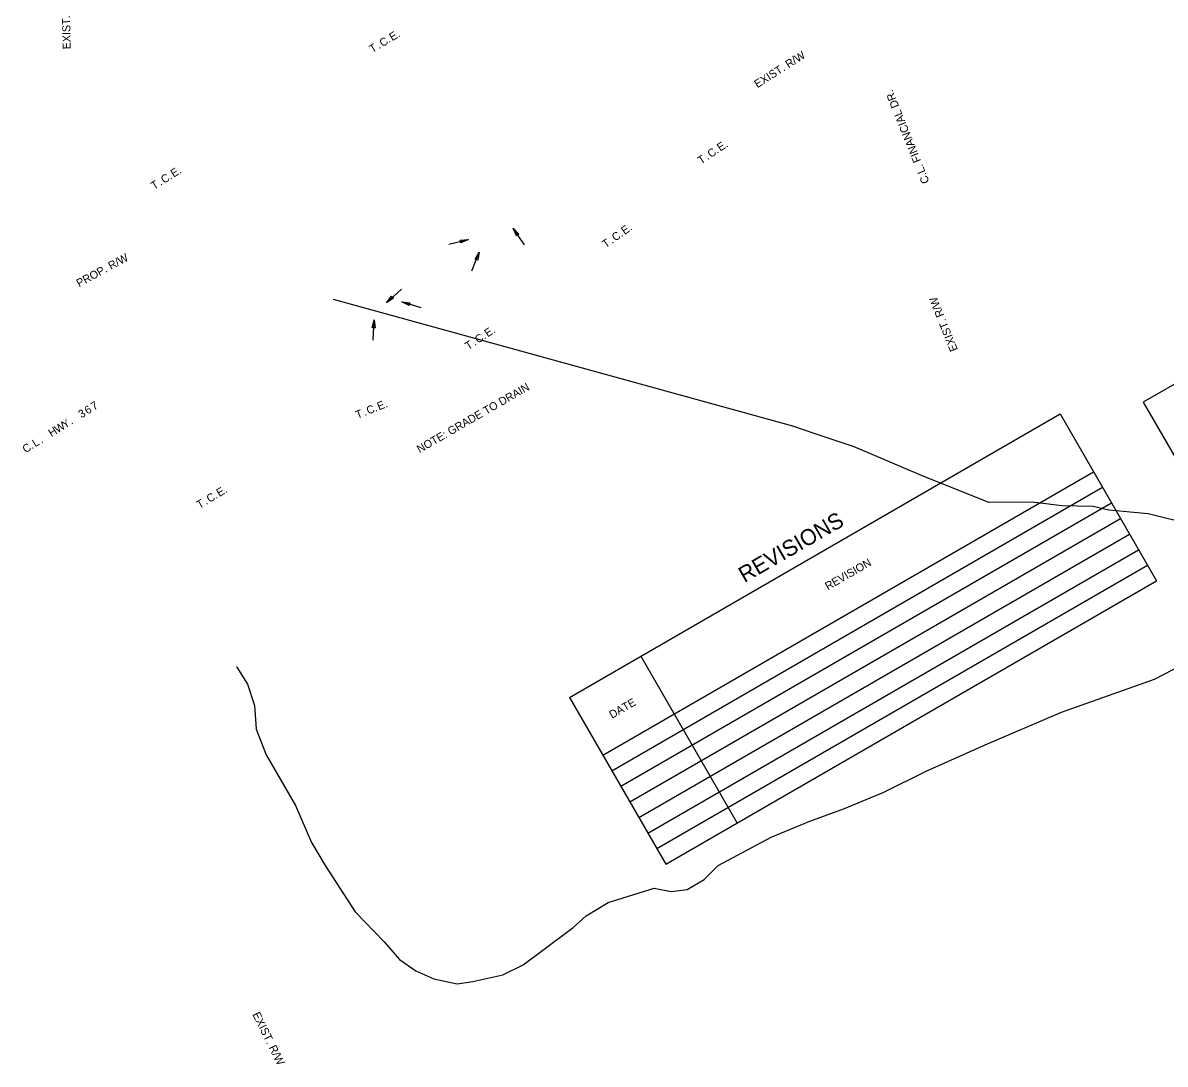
# Model space of a CAD drawing. Extents: x 1293866 to 1295382, y 223015 to 224618.
# Drawn here: x 1293866 to 1294723, y 223015 to 223796 of the extents above; entities that cross this region are included whole.
import ezdxf

# ---------------------------------------------------------------- set-up
doc = ezdxf.new("R2010")
doc.units = 0
for name, color, linetype in [('1', 7, 'Continuous'), ('10Tan10', 7, 'Continuous'), ('19', 7, 'Continuous'), ('43', 7, 'Continuous'), ('Default', 7, 'Continuous'), ('R_Draft', 7, 'Continuous'), ('S_TREE', 7, 'Continuous')]:
    doc.layers.add(name, color=color, linetype=linetype)

msp = doc.modelspace()

# ---------------------------------------------------------------- linework, layer by layer
at = {"layer": '1'}
msp.add_line((1295002.97, 223683.01), (1294706.22, 223511.68), dxfattribs=at)
msp.add_lwpolyline([(1294706.22, 223511.68), (1294766.75, 223406.85), (1295063.5, 223578.18)], dxfattribs=at)
at = {"layer": '19'}
for p, q in [((1294275.84, 223290.28), (1294643.9, 223502.78)), ((1294643.9, 223502.78), (1294716.15, 223377.64)), ((1294300.84, 223246.98), (1294668.9, 223459.48)), ((1294307.59, 223235.29), (1294675.65, 223447.79)), ((1294314.34, 223223.59), (1294682.4, 223436.09)), ((1294321.09, 223211.9), (1294689.15, 223424.4)), ((1294321.09, 223211.9), (1294689.15, 223424.4)), ((1294327.84, 223200.21), (1294695.9, 223412.71)), ((1294334.59, 223188.52), (1294702.65, 223401.02)), ((1294341.34, 223176.83), (1294709.4, 223389.33)), ((1294348.09, 223165.14), (1294716.15, 223377.64)), ((1294329.37, 223321.18), (1294401.62, 223196.04)), ((1294275.84, 223290.28), (1294348.09, 223165.14))]:
    msp.add_line(p, q, dxfattribs=at)
at = {"layer": '43'}
for p, q in [((1294233.62, 223642.03), (1294237.97, 223637.66)), ((1294236.21, 223636.44), (1294233.62, 223642.03)), ((1294194.07, 223633.22), (1294200.23, 223633.58)), ((1294194.57, 223631.13), (1294194.07, 223633.22)), ((1294200.23, 223633.58), (1294194.57, 223631.13)), ((1294237.97, 223637.66), (1294236.21, 223636.44)), ((1294205.08, 223618.97), (1294208.29, 223624.24)), ((1294208.29, 223624.24), (1294207.08, 223618.19)), ((1294207.08, 223618.19), (1294205.08, 223618.97)), ((1294138.66, 223586.24), (1294142.45, 223591.11)), ((1294143.89, 223589.52), (1294138.66, 223586.24)), ((1294142.45, 223591.11), (1294143.89, 223589.52)), ((1294150.13, 223586.84), (1294156.25, 223586.09)), ((1294155.63, 223584.04), (1294150.13, 223586.84)), ((1294156.25, 223586.09), (1294155.63, 223584.04)), ((1294128.09, 223567.34), (1294129.42, 223573.37)), ((1294129.42, 223573.37), (1294130.24, 223567.26)), ((1294130.24, 223567.26), (1294128.09, 223567.34))]:
    msp.add_line(p, q, dxfattribs=at)
for points in [[(1294242.29, 223629.57), (1294233.62, 223642.03)], [(1294185.45, 223630.08), (1294200.23, 223633.58)], [(1294202.77, 223610.09), (1294208.29, 223624.24)], [(1294149.93, 223596.42), (1294138.66, 223586.24)], [(1294164.66, 223582.4), (1294150.13, 223586.84)], [(1294128.79, 223558.2), (1294129.42, 223573.37)]]:
    msp.add_lwpolyline(points, dxfattribs=at)
at = {"layer": 'S_TREE'}
for points in [[(1294741.11, 223420.17), (1294709.95, 223427.78), (1294680.44, 223430.53), (1294668.71, 223433.36), (1294645.06, 223433.94), (1294623.05, 223436.57), (1294590.5, 223436.36), (1294539.79, 223456.62), (1294489.32, 223478.03), (1294460.84, 223487.63), (1294443.51, 223493.56), (1294098.95, 223588.59)], [(1294741.11, 223420.17), (1294709.95, 223427.78), (1294680.44, 223430.53), (1294668.71, 223433.36), (1294645.06, 223433.94), (1294623.05, 223436.57), (1294590.5, 223436.36), (1294539.79, 223456.62), (1294489.32, 223478.03), (1294460.84, 223487.63), (1294443.51, 223493.56), (1294098.95, 223588.59)], [(1294026.12, 223313.39), (1294026.44, 223312.93), (1294034.41, 223300.06), (1294039.65, 223284.29), (1294040.93, 223266.46), (1294048.46, 223247.28), (1294070.41, 223209.15), (1294082.4, 223181.33), (1294092.61, 223164.13), (1294115.34, 223129.4), (1294136.94, 223106.87), (1294148.52, 223093.75), (1294160.78, 223085.28), (1294174.29, 223079.08), (1294191.59, 223075.33), (1294203.5, 223077.21), (1294225.94, 223082.16), (1294241.14, 223089.78), (1294255.85, 223100.7), (1294278.59, 223117.58), (1294288.45, 223126.49), (1294304.9, 223136.38), (1294339.34, 223147.18), (1294352.2, 223144.65), (1294364.26, 223146.16), (1294376.91, 223153.6), (1294387.43, 223164.09), (1294427.14, 223185.39), (1294456.24, 223197.48), (1294482.07, 223206.89), (1294511.54, 223219.13), (1294543.44, 223235), (1294587.74, 223254.71), (1294644.84, 223279.28), (1294714.57, 223303.99), (1294748.77, 223321.6)], [(1294026.12, 223313.39), (1294026.44, 223312.93), (1294034.41, 223300.06), (1294039.65, 223284.29), (1294040.93, 223266.46), (1294048.46, 223247.28), (1294070.41, 223209.15), (1294082.4, 223181.33), (1294092.61, 223164.13), (1294115.34, 223129.4), (1294136.94, 223106.87), (1294148.52, 223093.75), (1294160.78, 223085.28), (1294174.29, 223079.08), (1294191.59, 223075.33), (1294203.5, 223077.21), (1294225.94, 223082.16), (1294241.14, 223089.78), (1294255.85, 223100.7), (1294278.59, 223117.58), (1294288.45, 223126.49), (1294304.9, 223136.38), (1294339.34, 223147.18), (1294352.2, 223144.65), (1294364.26, 223146.16), (1294376.91, 223153.6), (1294387.43, 223164.09), (1294427.14, 223185.39), (1294456.24, 223197.48), (1294482.07, 223206.89), (1294511.54, 223219.13), (1294543.44, 223235), (1294587.74, 223254.71), (1294644.84, 223279.28), (1294714.57, 223303.99), (1294748.77, 223321.6)]]:
    msp.add_lwpolyline(points, dxfattribs=at)

# ---------------------------------------------------------------- texts
at = {"layer": '10Tan10'}
for s, rotation, p in [('EXIST. R/W & C/A', 91.19347, (1293901.92, 223776.28)), ('EXIST. R/W', 32.42629, (1294416.84, 223747.02)), ('PROP. R/W', 28.60191, (1293908.19, 223597.75)), ('EXIST. R/W', 111.79541, (1294567.23, 223551.03)), ('EXIST. R/W', 296.21548, (1294038.04, 223052.53))]:
    msp.add_text(s, height=6, rotation=rotation, dxfattribs=at).set_placement(p)
at = {"layer": '19'}
for s, height, p in [('REVISIONS', 12, (1294407.12, 223375.89)), ('REVISION', 6, (1294469.71, 223370.45)), ('DATE', 6, (1294307.85, 223274.12))]:
    msp.add_text(s, height=height, rotation=30.00011, dxfattribs=at).set_placement(p)
at = {"layer": 'Default'}
for s, rotation, p in [('C.L. FINANCIAL DR.', 111.83333, (1294545.96, 223676.88)), ('7', 31.99396, (1293919.33, 223505.25)), ('3', 31.99396, (1293909.96, 223499.39)), ('6', 31.99396, (1293914.53, 223502.25)), ('W', 31.99396, (1293892.05, 223488.2)), ('Y', 31.99396, (1293897.5, 223491.61)), ('.', 31.99396, (1293902.39, 223494.66)), ('H', 31.99396, (1293887.48, 223485.35)), ('C', 31.99396, (1293868.05, 223473.21)), ('L', 31.99396, (1293875.34, 223477.76)), ('.', 31.99396, (1293872.86, 223476.21)), ('.', 31.99396, (1293879.91, 223480.62))]:
    msp.add_text(s, height=6, rotation=rotation, dxfattribs=at).set_placement(p)
at = {"layer": 'R_Draft'}
for s, rotation, p in [('E', 30.9348, (1294142.99, 223782.24)), ('.', 30.9348, (1294147.61, 223785.01)), ('T', 30.9348, (1294128.08, 223773.3)), ('.', 30.9348, (1294133.1, 223776.32)), ('C', 30.9348, (1294135.62, 223777.82)), ('.', 30.9348, (1294140.48, 223780.74)), ('C', 34.00129, (1294381.88, 223694.64)), ('E', 34.00129, (1294389.01, 223699.45)), ('.', 34.00129, (1294393.47, 223702.46)), ('T', 34.00129, (1294374.6, 223689.72)), ('.', 34.00129, (1294379.45, 223693)), ('.', 34.00129, (1294386.58, 223697.81)), ('C', 32.15368, (1293971.85, 223675.36)), ('E', 32.15368, (1293979.13, 223679.94)), ('.', 32.15368, (1293983.69, 223682.8)), ('T', 32.15368, (1293964.41, 223670.68)), ('.', 32.15368, (1293969.37, 223673.8)), ('.', 32.15368, (1293976.65, 223678.38)), ('E', 35.33351, (1294317.28, 223636.96)), ('.', 35.33351, (1294321.67, 223640.08)), ('T', 35.33351, (1294303.09, 223626.91)), ('.', 35.33351, (1294307.87, 223630.29)), ('C', 35.33351, (1294310.26, 223631.99)), ('.', 35.33351, (1294314.89, 223635.27)), ('C', 33.48443, (1294207.4, 223555.4)), ('E', 33.48443, (1294214.58, 223560.14)), ('.', 33.48443, (1294219.07, 223563.11)), ('T', 33.48443, (1294200.08, 223550.55)), ('.', 33.48443, (1294204.96, 223553.78)), ('.', 33.48443, (1294212.13, 223558.52)), ('NOTE: GRADE TO DRAIN', 30, (1294163.58, 223473.28)), ('E', 21.6622, (1294133.08, 223505.44)), ('T', 21.6622, (1294116.92, 223499.02)), ('C', 21.6622, (1294125.09, 223502.27)), ('.', 21.6622, (1294130.36, 223504.36)), ('.', 21.6622, (1294138.09, 223507.43)), ('.', 21.6622, (1294122.37, 223501.18)), ('C', 30.9348, (1294005.99, 223436.04)), ('E', 30.9348, (1294013.37, 223440.46)), ('.', 30.9348, (1294017.99, 223443.23)), ('T', 30.9348, (1293998.46, 223431.52)), ('.', 30.9348, (1294003.48, 223434.53)), ('.', 30.9348, (1294010.86, 223438.95))]:
    msp.add_text(s, height=6, rotation=rotation, dxfattribs=at).set_placement(p)

doc.saveas('drawing.dxf')
